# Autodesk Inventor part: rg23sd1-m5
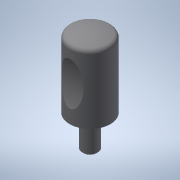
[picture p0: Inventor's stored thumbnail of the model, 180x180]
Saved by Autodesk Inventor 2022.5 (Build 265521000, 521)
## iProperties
Created: 2016-12
Part Number: rg23sd1-m5
Material: 一般
Document SubType Name: Modeling
Designer: imaocorp
Density: 1 g/cm^3
Appearance: 既定
Author: imaocorp
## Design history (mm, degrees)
node "rg23sd1-m5.x_t1"
node "rg23sd1-m5"
node "Base1"
